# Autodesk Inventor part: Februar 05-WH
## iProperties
Created: 2005-02
Part Number: Februar 05-WH
Document SubType Name: Modeling
Designer: W. Holzwarth
Manufacturer: Standard
Standards Organization: Custom
Author: W. Holzwarth
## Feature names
1. Extrusion1
2. Extrusion2
3. Trennen1
4. Flächenverjüngung1
5. Extrusion11
6. Extrusion4
7. Rundung2 [Fillet]
8. Extrusion5
9. Extrusion6
10. Spiegeln1 [Mirror]
11. Drehung1 [Revolution]
12. Extrusion7
13. Extrusion13
14. Spiegeln2 [Mirror]
15. Extrusion8
16. Extrusion9
17. Extrusion10
18. Rundung3 [Fillet]
19. Rundung7 [Fillet]
20. Rundung8 [Fillet]
21. Erhebung1
22. Rundung17 [Fillet]
23. Spiegeln3 [Mirror]
24. Rundung18 [Fillet]
25. Rundung12 [Fillet]
26. Rundung13 [Fillet]
27. Rundung14 [Fillet]
28. Rundung15 [Fillet]
29. Rundung19 [Fillet]
